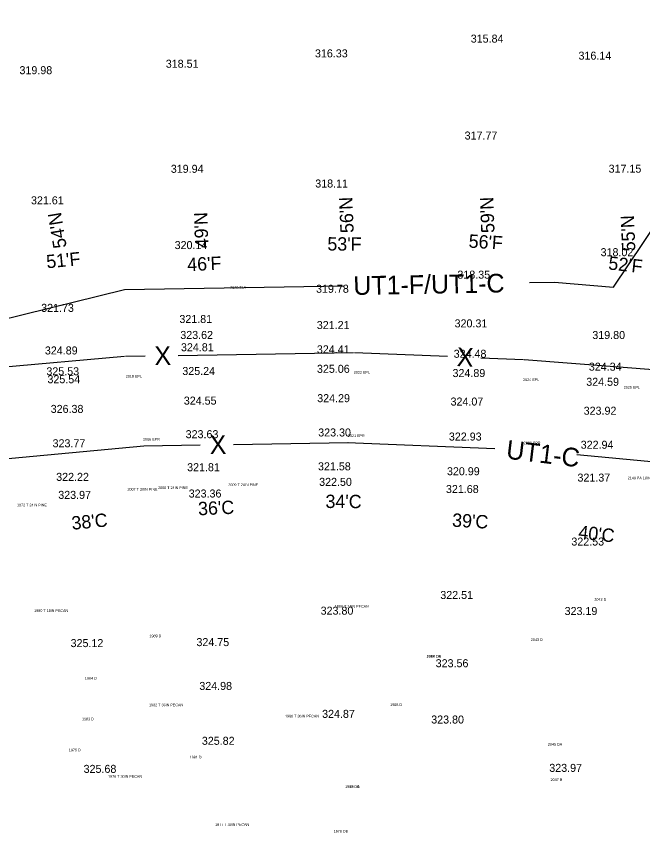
# Model space of a CAD drawing. Extents: x 49683 to 58852, y 49596 to 54801.
# Drawn here: x 56682.9 to 56917.7, y 53906.8 to 54212.6 of the extents above; entities that cross this region are included whole.
import ezdxf

# ---------------------------------------------------------------- set-up
doc = ezdxf.new("R2010")
doc.units = 0
for name, color, linetype in [('Level 2', 7, 'Continuous'), ('Level 3', 7, 'Continuous'), ('Level 32', 7, 'Continuous'), ('Level 4', 7, 'Continuous'), ('Level 48', 7, 'Continuous'), ('Level 53', 7, 'Continuous'), ('Level 56', 7, 'Continuous'), ('Level 58', 7, 'Continuous'), ('Level 61', 7, 'Continuous')]:
    doc.layers.add(name, color=color, linetype=linetype)

msp = doc.modelspace()

# ---------------------------------------------------------------- linework, layer by layer
at = {"layer": 'Level 2'}
for p, q in [((56641.28, 54078.02), (56723.47, 54085.22)), ((56723.82, 54085.24), (56731.14, 54085.36)), ((56743.59, 54085.57), (56809.27, 54086.7)), ((56809.57, 54086.7), (56844.51, 54085.22)), ((56856.96, 54084.69), (56873.03, 54084.01)), ((56873.2, 54084), (56938.47, 54078.98)), ((56654.76, 54044.56), (56730.64, 54051.66)), ((56730.64, 54051.66), (56751.83, 54052.02)), ((56764.28, 54052.23), (56807.22, 54052.96)), ((56806.93, 54052.96), (56862.26, 54050.7)), ((56892.99, 54048.39), (56923.55, 54045.55))]:
    msp.add_line(p, q, dxfattribs=at)
at = {"layer": 'Level 3'}
for p, q in [((56723.39, 54110.23), (56805.68, 54111.64)), ((56875.28, 54112.84), (56884.55, 54113)), ((56605.08, 54081.22), (56723.39, 54110.23))]:
    msp.add_line(p, q, dxfattribs=at)
msp.add_lwpolyline([(56884.55, 54113), (56906.74, 54111.13), (56974.99, 54212.59)], dxfattribs=at)

# ---------------------------------------------------------------- texts
at = {"layer": 'Level 2'}
msp.add_text('UT1-C', height=7, rotation=353.1281, dxfattribs=at).set_placement((56866.22, 54046.93))
at = {"layer": 'Level 32'}
for s, p in [('315.84', (56853.2, 54202.74)), ('316.33', (56794.81, 54197.21)), ('316.14', (56893.6, 54196.36)), ('318.51', (56738.89, 54193.33)), ('319.98', (56684.05, 54190.91)), ('317.77', (56850.91, 54166.43)), ('319.94', (56740.77, 54153.97)), ('317.15', (56904.88, 54154.01)), ('318.11', (56794.92, 54148.46)), ('321.61', (56688.36, 54142.16)), ('320.14', (56742.21, 54125.4)), ('318.02', (56901.88, 54122.73)), ('318.35', (56848.2, 54114.32)), ('319.78', (56795.22, 54109.03)), ('321.73', (56692.17, 54101.88)), ('321.81', (56743.99, 54097.7)), ('321.21', (56795.5, 54095.44)), ('320.31', (56847.15, 54096.06)), ('323.62', (56744.33, 54091.73)), ('319.80', (56898.77, 54091.7)), ('324.81', (56744.58, 54087.12)), ('324.89', (56693.57, 54085.92)), ('324.41', (56795.52, 54086.33)), ('324.48', (56846.81, 54084.68)), ('325.53', (56694.13, 54078.12)), ('325.24', (56745.09, 54078.23)), ('325.06', (56795.56, 54079.04)), ('324.34', (56897.47, 54079.84)), ('325.54', (56694.54, 54075.14)), ('324.89', (56846.38, 54077.45)), ('324.59', (56896.5, 54074.18)), ('324.55', (56745.65, 54067.13)), ('324.29', (56795.66, 54068.04)), ('324.07', (56845.64, 54066.78)), ('326.38', (56695.75, 54064.02)), ('323.92', (56895.53, 54063.34)), ('323.63', (56746.34, 54054.55)), ('323.30', (56796.03, 54055.2)), ('322.93', (56845.01, 54053.67)), ('323.77', (56696.46, 54051.15)), ('322.94', (56894.42, 54050.6)), ('321.81', (56746.89, 54042.18)), ('321.58', (56795.95, 54042.51)), ('322.22', (56697.81, 54038.56)), ('320.99', (56844.29, 54040.67)), ('321.37', (56893.21, 54038.29)), ('322.50', (56796.38, 54036.69)), ('323.36', (56747.48, 54032.33)), ('321.68', (56843.91, 54034.01)), ('323.97', (56698.59, 54031.81)), ('322.53', (56890.92, 54014.33)), ('322.51', (56841.79, 53994.32)), ('323.80', (56796.93, 53988.44)), ('323.19', (56888.39, 53988.31)), ('325.12', (56703.21, 53976.29)), ('324.75', (56750.38, 53976.66)), ('323.56', (56840.06, 53968.75)), ('324.98', (56751.46, 53960.24)), ('324.87', (56797.49, 53949.78)), ('323.80', (56838.39, 53947.66)), ('325.82', (56752.41, 53939.69)), ('325.68', (56708.09, 53929.17)), ('323.97', (56882.65, 53929.55))]:
    msp.add_text(s, height=3, dxfattribs=at).set_placement(p)
at = {"layer": 'Level 4'}
for s, rotation, p in [('UT1-F/UT1-C', 0.9828, (56809.24, 54108.2)), ('X', 0.9828, (56734.69, 54081.92)), ('X', 357.5715, (56847.86, 54081.57)), ('X', 0.9705, (56755.38, 54048.58))]:
    msp.add_text(s, height=7, rotation=rotation, dxfattribs=at).set_placement(p)
at = {"layer": 'Level 48'}
for s, rotation, p in [("56'N", 92.1896, (56809.35, 54131.5)), ("59'N", 92.1896, (56862.14, 54131.5)), ("54'N", 99.3793, (56701.77, 54126.12)), ("49'N", 92.1896, (56754.91, 54125.79)), ("55'N", 92.1896, (56914.93, 54124.64)), ("53'F", 359.5783, (56799.45, 54124.87)), ("56'F", 356.6096, (56852.31, 54125.96)), ("51'F", 5.5156, (56694.34, 54118.16)), ("46'F", 2.547, (56747.04, 54117.11)), ("52'F", 353.6409, (56904.59, 54117.78)), ("34'C", 359.5783, (56798.74, 54028.41)), ("36'C", 2.547, (56751.1, 54025.64)), ("38'C", 5.5157, (56703.79, 54020.22)), ("39'C", 356.6096, (56846.12, 54021.44)), ("40'C", 353.6409, (56893.35, 54016.98))]:
    msp.add_text(s, height=5, rotation=rotation, dxfattribs=at).set_placement(p)
at = {"layer": 'Level 53'}
for s, p in [('2019 EPL ', (56723.9, 54077.24)), ('2022 EPL ', (56809.36, 54078.7)), ('2024 EPL ', (56872.82, 54076.01)), ('2025 EPL ', (56910.53, 54073.11)), ('2006 EPR ', (56730.36, 54053.66)), ('2021 EPR ', (56807.13, 54054.96)), ('2023 EPR ', (56873.04, 54052.26))]:
    msp.add_text(s, height=1, dxfattribs=at).set_placement(p)
at = {"layer": 'Level 56'}
msp.add_text('2149 PA 18IN RC ', height=1, dxfattribs=at).set_placement((56912.03, 54039.18))
at = {"layer": 'Level 58'}
for s, p in [('2042 D ', (56899.53, 53993.66)), ('1989 D ', (56732.77, 53979.97)), ('2043 D ', (56875.73, 53978.59)), ('2044 DB ', (56836.66, 53972.32)), ('1987 DA ', (56836.66, 53972.32)), ('1984 D ', (56708.57, 53964.14)), ('1985 D ', (56823.01, 53954.2)), ('1983 D ', (56707.47, 53948.83)), ('2045 DA ', (56882.11, 53939.38)), ('1975 D ', (56702.53, 53937.27)), ('1981 D ', (56747.83, 53934.57)), ('2047 B ', (56883.11, 53926.12)), ('1979 DA ', (56806.15, 53923.5)), ('1986 DB ', (56806.15, 53923.5)), ('1978 DB ', (56801.83, 53906.79))]:
    msp.add_text(s, height=1, dxfattribs=at).set_placement(p)
at = {"layer": 'Level 61'}
for s, p in [('2020 TLA ', (56763.02, 54110.51)), ('2007 T 30IN PINE ', (56724.52, 54034.91)), ('2008 T 24IN PINE ', (56735.97, 54035.49)), ('2009 T 24IN PINE ', (56762.31, 54036.59)), ('1972 T 24IN PINE ', (56683.1, 54029)), ('1990 T 18IN PECAN ', (56689.55, 53989.45)), ('1988 T 24IN PECAN ', (56802.24, 53991.01)), ('1982 T 36IN PECAN ', (56732.63, 53954.14)), ('1980 T 36IN PECAN ', (56783.57, 53949.92)), ('1976 T 30IN PECAN ', (56717.25, 53927.33)), ('1977 T 40IN PECAN ', (56757.4, 53909.32))]:
    msp.add_text(s, height=1, dxfattribs=at).set_placement(p)

doc.saveas('drawing.dxf')
